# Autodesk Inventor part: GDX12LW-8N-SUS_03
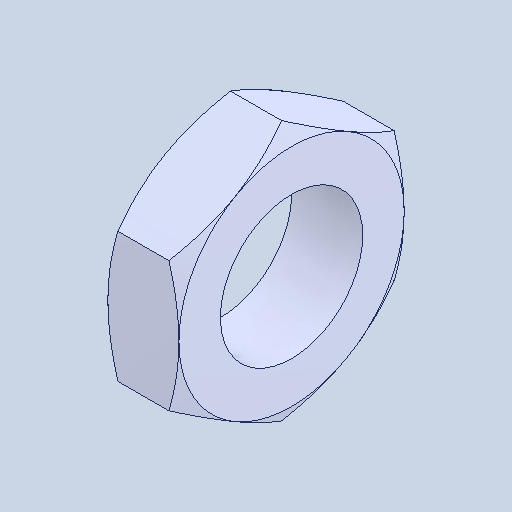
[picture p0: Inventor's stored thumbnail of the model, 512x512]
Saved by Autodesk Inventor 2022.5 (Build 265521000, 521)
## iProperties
Created: 2024-06
Part Number: GDX12LW-8N-SUS_03
Material: 一般
Document SubType Name: Modeling
Designer: ImaoCorp
Density: 1 g/cm^3
Appearance: 既定
Author: ImaoCorp
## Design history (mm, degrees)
feature "GDX12LW-8N-SUS_03"
node "ソリッド1"
